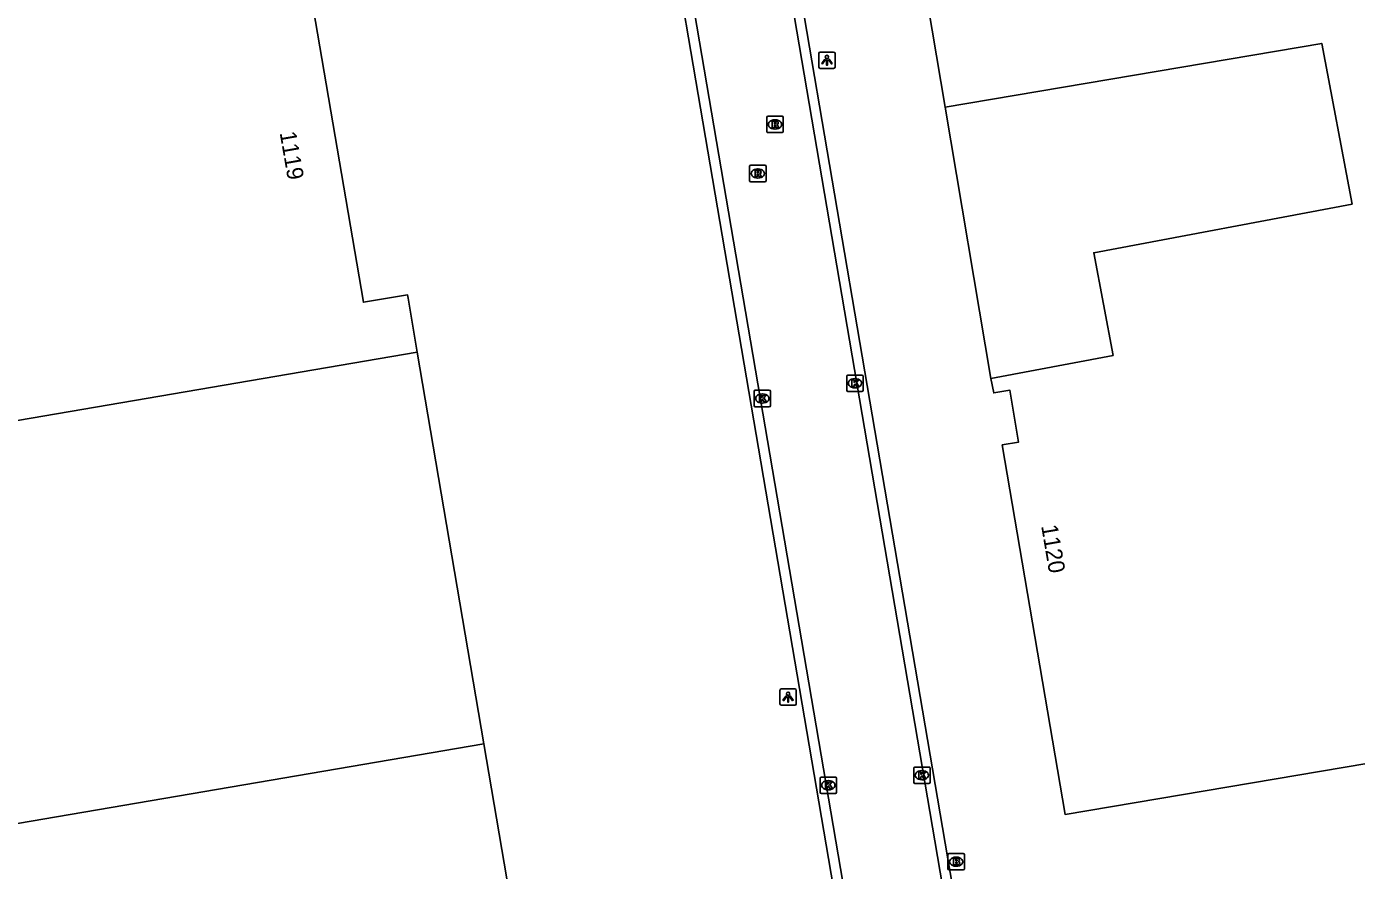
# Model space of a CAD drawing. Extents: x 154324 to 155743, y 382939 to 384183.
# Drawn here: x 154878.9 to 154959.7, y 383380.6 to 383431.9 of the extents above; entities that cross this region are included whole.
import ezdxf

# ---------------------------------------------------------------- set-up
doc = ezdxf.new("R2010")
doc.units = 0
for name, color, linetype in [('IMGEO_Brandkraan', 7, 'Continuous'), ('IMGEO_Hek', 7, 'Continuous'), ('IMGEO_Kolk', 7, 'Continuous'), ('IMGEO_Lichtpunt', 7, 'Continuous'), ('IMGEO_Pand', 7, 'Continuous'), ('IMGEO_Pand_nummerreeks', 7, 'Continuous'), ('IMGEO_Pand_overbouw', 7, 'Continuous'), ('IMGEO_Rijbaan_lokaal_gesloten', 7, 'Continuous'), ('IMGEO_Rijbaan_lokaal_open', 7, 'Continuous'), ('IMGEO_Rioolput', 7, 'Continuous')]:
    doc.layers.add(name, color=color, linetype=linetype)

msp = doc.modelspace()

# ---------------------------------------------------------------- linework, layer by layer
at = {"layer": 'IMGEO_Brandkraan'}
for p, q in [((154934.862, 383380.692), (154934.862, 383381.544)), ((154934.937, 383381.618), (154935.789, 383381.618)), ((154935.35, 383381.398), (154935.375, 383381.398)), ((154935.863, 383381.544), (154935.863, 383380.692)), ((154935.789, 383380.618), (154934.937, 383380.618)), ((154935.373, 383380.838), (154935.348, 383380.838))]:
    msp.add_line(p, q, dxfattribs=at)
for points in [[(154934.862, 383380.692), (154934.862, 383381.544)], [(154934.937, 383381.618), (154935.789, 383381.618)], [(154935.21, 383381.318), (154935.21, 383380.918), (154935.423, 383380.918)], [(154935.441, 383381.318), (154935.21, 383381.318)], [(154935.389, 383381.237), (154935.335, 383381.237), (154935.335, 383381.161)], [(154935.863, 383381.544), (154935.863, 383380.692)], [(154935.789, 383380.618), (154934.937, 383380.618)], [(154935.335, 383381.161), (154935.388, 383381.161)], [(154935.397, 383381.085), (154935.335, 383381.085), (154935.335, 383381.004)], [(154935.335, 383381.004), (154935.397, 383381.004)]]:
    msp.add_lwpolyline(points, dxfattribs=at)
for centre, radius, start, end in [((154934.939, 383381.542), 0.0765, 91.55205, 178.44795), ((154934.939, 383381.542), 0.0765, 91.55205, 178.44795), ((154935.39, 383381.199), 0.0379, 267.82845, 90.93552), ((154935.445, 383381.173), 0.145, 59.4692, 91.53667), ((154935.47, 383381.22), 0.0922, 285.51372, 58.15012), ((154935.787, 383381.542), 0.0765, 1.55205, 88.44795), ((154935.787, 383381.542), 0.0765, 1.55205, 88.44795), ((154934.939, 383380.694), 0.0765, 181.55205, 268.44795), ((154934.939, 383380.694), 0.0765, 181.55205, 268.44795), ((154935.398, 383381.044), 0.0404, 269.87594, 90.50774), ((154935.429, 383381.169), 0.251, 268.66757, 293.53466), ((154935.475, 383381.028), 0.105, 301.31148, 78.98903), ((154935.787, 383380.694), 0.0765, 271.55205, 358.44795), ((154935.787, 383380.694), 0.0765, 271.55205, 358.44795)]:
    msp.add_arc(centre, radius, start, end, dxfattribs=at)
for centre, major_axis, ratio, start_param, end_param in [((154935.349, 383381.118), (-0.387, 0.002), 0.722429, 4.712389, 7.853982), ((154935.374, 383381.118), (-0.39, 0.002), 0.717154, 1.570796, 4.712389)]:
    msp.add_ellipse(centre, major_axis=major_axis, ratio=ratio, start_param=start_param, end_param=end_param, dxfattribs=at)
at = {"layer": 'IMGEO_Hek'}
msp.add_lwpolyline([(154902.623, 383412.072), (154906.674, 383388.272)], dxfattribs=at)
at = {"layer": 'IMGEO_Kolk'}
for p, q in [((154928.715, 383409.766), (154928.715, 383410.618)), ((154928.79, 383410.692), (154929.642, 383410.692)), ((154929.203, 383410.472), (154929.228, 383410.472)), ((154929.716, 383410.618), (154929.716, 383409.766)), ((154923.088, 383408.839), (154923.088, 383409.691)), ((154923.163, 383409.765), (154924.015, 383409.765)), ((154923.576, 383409.545), (154923.601, 383409.545)), ((154924.089, 383409.691), (154924.089, 383408.839)), ((154929.642, 383409.692), (154928.79, 383409.692)), ((154929.226, 383409.912), (154929.201, 383409.912)), ((154924.015, 383408.765), (154923.163, 383408.765)), ((154923.599, 383408.985), (154923.574, 383408.985)), ((154932.859, 383386.872), (154933.711, 383386.872)), ((154927.099, 383385.338), (154927.099, 383386.19)), ((154927.174, 383386.264), (154928.026, 383386.264)), ((154928.1, 383386.19), (154928.1, 383385.338)), ((154932.784, 383385.946), (154932.784, 383386.798)), ((154933.295, 383386.092), (154933.27, 383386.092)), ((154933.272, 383386.652), (154933.297, 383386.652)), ((154933.785, 383386.798), (154933.785, 383385.946)), ((154928.026, 383385.264), (154927.174, 383385.264)), ((154927.61, 383385.484), (154927.585, 383385.484)), ((154927.587, 383386.044), (154927.612, 383386.044)), ((154933.711, 383385.872), (154932.859, 383385.872))]:
    msp.add_line(p, q, dxfattribs=at)
for points in [[(154928.715, 383409.766), (154928.715, 383410.618)], [(154928.79, 383410.692), (154929.642, 383410.692)], [(154929.036, 383410.392), (154929.159, 383410.392), (154929.159, 383410.241), (154929.289, 383410.392), (154929.453, 383410.392), (154929.307, 383410.241), (154929.46, 383409.992), (154929.308, 383409.992), (154929.223, 383410.156), (154929.159, 383410.089), (154929.159, 383409.992), (154929.036, 383409.992), (154929.036, 383410.392)], [(154929.716, 383410.618), (154929.716, 383409.766)], [(154923.088, 383408.839), (154923.088, 383409.691)], [(154923.163, 383409.765), (154924.015, 383409.765)], [(154924.089, 383409.691), (154924.089, 383408.839)], [(154929.642, 383409.692), (154928.79, 383409.692)], [(154924.015, 383408.765), (154923.163, 383408.765)], [(154923.409, 383409.465), (154923.532, 383409.465), (154923.532, 383409.314), (154923.662, 383409.465), (154923.826, 383409.465), (154923.68, 383409.314), (154923.833, 383409.065), (154923.681, 383409.065), (154923.596, 383409.229), (154923.532, 383409.162), (154923.532, 383409.065), (154923.409, 383409.065), (154923.409, 383409.465)], [(154932.859, 383386.872), (154933.711, 383386.872)], [(154927.099, 383385.338), (154927.099, 383386.19)], [(154927.174, 383386.264), (154928.026, 383386.264)], [(154928.1, 383386.19), (154928.1, 383385.338)], [(154932.784, 383385.946), (154932.784, 383386.798)], [(154933.105, 383386.572), (154933.228, 383386.572), (154933.228, 383386.421), (154933.358, 383386.572), (154933.522, 383386.572), (154933.376, 383386.421), (154933.529, 383386.172), (154933.377, 383386.172), (154933.292, 383386.336), (154933.228, 383386.269), (154933.228, 383386.172), (154933.105, 383386.172), (154933.105, 383386.572)], [(154933.785, 383386.798), (154933.785, 383385.946)], [(154928.026, 383385.264), (154927.174, 383385.264)], [(154927.42, 383385.964), (154927.543, 383385.964), (154927.543, 383385.813), (154927.673, 383385.964), (154927.837, 383385.964), (154927.691, 383385.813), (154927.844, 383385.564), (154927.692, 383385.564), (154927.607, 383385.728), (154927.543, 383385.661), (154927.543, 383385.564), (154927.42, 383385.564), (154927.42, 383385.964)], [(154933.711, 383385.872), (154932.859, 383385.872)]]:
    msp.add_lwpolyline(points, dxfattribs=at)
for centre, start, end in [((154928.792, 383410.616), 91.55205, 178.44795), ((154928.792, 383410.616), 91.55205, 178.44795), ((154929.64, 383410.616), 1.55205, 88.44795), ((154929.64, 383410.616), 1.55205, 88.44795), ((154923.165, 383409.689), 91.55205, 178.44795), ((154923.165, 383409.689), 91.55205, 178.44795), ((154924.013, 383409.689), 1.55205, 88.44795), ((154924.013, 383409.689), 1.55205, 88.44795), ((154928.792, 383409.768), 181.55205, 268.44795), ((154928.792, 383409.768), 181.55205, 268.44795), ((154929.64, 383409.768), 271.55205, 358.44795), ((154929.64, 383409.768), 271.55205, 358.44795), ((154923.165, 383408.841), 181.55205, 268.44795), ((154923.165, 383408.841), 181.55205, 268.44795), ((154924.013, 383408.841), 271.55205, 358.44795), ((154924.013, 383408.841), 271.55205, 358.44795), ((154932.861, 383386.796), 91.55205, 178.44795), ((154932.861, 383386.796), 91.55205, 178.44795), ((154933.709, 383386.796), 1.55205, 88.44795), ((154933.709, 383386.796), 1.55205, 88.44795), ((154927.176, 383386.188), 91.55205, 178.44795), ((154927.176, 383386.188), 91.55205, 178.44795), ((154928.024, 383386.188), 1.55205, 88.44795), ((154928.024, 383386.188), 1.55205, 88.44795), ((154927.176, 383385.34), 181.55205, 268.44795), ((154927.176, 383385.34), 181.55205, 268.44795), ((154928.024, 383385.34), 271.55205, 358.44795), ((154928.024, 383385.34), 271.55205, 358.44795), ((154932.861, 383385.948), 181.55205, 268.44795), ((154932.861, 383385.948), 181.55205, 268.44795), ((154933.709, 383385.948), 271.55205, 358.44795), ((154933.709, 383385.948), 271.55205, 358.44795)]:
    msp.add_arc(centre, 0.0765, start, end, dxfattribs=at)
for centre, major_axis, ratio, start_param, end_param in [((154929.202, 383410.192), (-0.387, 0.002), 0.722429, 4.712389, 7.853982), ((154929.227, 383410.192), (-0.39, 0.002), 0.717154, 1.570796, 4.712389), ((154923.575, 383409.265), (-0.387, 0.002), 0.722429, 4.712389, 7.853982), ((154923.6, 383409.265), (-0.39, 0.002), 0.717154, 1.570796, 4.712389), ((154933.271, 383386.372), (-0.387, 0.002), 0.722429, 4.712389, 7.853982), ((154933.296, 383386.372), (-0.39, 0.002), 0.717154, 1.570796, 4.712389), ((154927.586, 383385.764), (-0.387, 0.002), 0.722429, 4.712389, 7.853982), ((154927.611, 383385.764), (-0.39, 0.002), 0.717154, 1.570796, 4.712389)]:
    msp.add_ellipse(centre, major_axis=major_axis, ratio=ratio, start_param=start_param, end_param=end_param, dxfattribs=at)
at = {"layer": 'IMGEO_Lichtpunt'}
for p, q in [((154927.016, 383430.225), (154927.016, 383429.418)), ((154927.016, 383430.225), (154927.016, 383429.418)), ((154927.918, 383430.32), (154927.11, 383430.32)), ((154927.918, 383430.32), (154927.11, 383430.32)), ((154928.012, 383429.418), (154928.012, 383430.225)), ((154928.012, 383429.418), (154928.012, 383430.225)), ((154927.11, 383429.324), (154927.918, 383429.324)), ((154927.11, 383429.324), (154927.918, 383429.324)), ((154924.657, 383391.526), (154924.657, 383390.719)), ((154924.657, 383391.526), (154924.657, 383390.719)), ((154925.559, 383391.621), (154924.751, 383391.621)), ((154925.559, 383391.621), (154924.751, 383391.621)), ((154925.653, 383390.719), (154925.653, 383391.526)), ((154925.653, 383390.719), (154925.653, 383391.526)), ((154924.751, 383390.625), (154925.559, 383390.625)), ((154924.751, 383390.625), (154925.559, 383390.625))]:
    msp.add_line(p, q, dxfattribs=at)
for points in [[(154927.39, 383429.889), (154927.429, 383429.861), (154927.241, 383429.599), (154927.203, 383429.626), (154927.39, 383429.889)], [(154927.492, 383429.841), (154927.539, 383429.841), (154927.539, 383429.519), (154927.492, 383429.519), (154927.492, 383429.841)], [(154927.602, 383429.861), (154927.64, 383429.888), (154927.827, 383429.626), (154927.788, 383429.598), (154927.602, 383429.861)], [(154925.031, 383391.19), (154925.07, 383391.162), (154924.882, 383390.9), (154924.844, 383390.927), (154925.031, 383391.19)], [(154925.133, 383391.142), (154925.18, 383391.142), (154925.18, 383390.82), (154925.133, 383390.82), (154925.133, 383391.142)], [(154925.243, 383391.162), (154925.281, 383391.189), (154925.468, 383390.927), (154925.429, 383390.899), (154925.243, 383391.162)]]:
    msp.add_lwpolyline(points, dxfattribs=at)
for centre in [(154927.515, 383430.023), (154925.156, 383391.324)]:
    msp.add_circle(centre, 0.0994, dxfattribs=at)
for centre, start, end in [((154927.11, 383430.225), 90, 180), ((154927.11, 383430.225), 90, 180), ((154927.918, 383430.225), 0, 90), ((154927.918, 383430.225), 0, 90), ((154927.11, 383429.418), 180, 270), ((154927.11, 383429.418), 180, 270), ((154927.918, 383429.418), 270, 0), ((154927.918, 383429.418), 270, 360), ((154924.751, 383391.526), 90, 180), ((154924.751, 383391.526), 90, 180), ((154925.559, 383391.526), 0, 90), ((154925.559, 383391.526), 0, 90), ((154924.751, 383390.719), 180, 270), ((154924.751, 383390.719), 180, 270), ((154925.559, 383390.719), 270, 0), ((154925.559, 383390.719), 270, 360)]:
    msp.add_arc(centre, 0.0946, start, end, dxfattribs=at)
at = {"layer": 'IMGEO_Pand'}
for points in [[(154834.619, 383400.461), (154821.718, 383476.24), (154889.716, 383487.815), (154890.443, 383483.587), (154890.304, 383483.564), (154892.766, 383469.145), (154892.803, 383468.928), (154890.043, 383468.457), (154891.058, 383462.645), (154893.935, 383463.15), (154893.976, 383462.908), (154894.602, 383459.232), (154877.774, 383456.368), (154879.542, 383446.048), (154896.359, 383448.912), (154898.955, 383433.672), (154898.99, 383433.466), (154896.309, 383433.01), (154899.362, 383415.11), (154902.045, 383415.555), (154902.077, 383415.363), (154902.623, 383412.072), (154834.619, 383400.461)], [(154982.688, 383452.666), (154992.885, 383392.595), (154941.984, 383383.986), (154938.166, 383406.445), (154939.152, 383406.613), (154938.627, 383409.767), (154937.644, 383409.605), (154937.479, 383410.489), (154944.895, 383411.887), (154943.721, 383418.118), (154959.415, 383421.076), (154957.574, 383430.84), (154934.692, 383426.973), (154931.812, 383444.014), (154982.688, 383452.666)], [(154838.617, 383376.662), (154906.674, 383388.272), (154909.471, 383371.879), (154909.506, 383371.674), (154906.592, 383371.177), (154909.354, 383354.958), (154912.253, 383355.448), (154912.286, 383355.25), (154916.529, 383330.318), (154915.54, 383330.141), (154917.365, 383319.49), (154915.455, 383319.155), (154917.904, 383304.636), (154920.822, 383305.041), (154920.858, 383304.829), (154920.912, 383304.514), (154852.875, 383292.89), (154838.617, 383376.662)]]:
    msp.add_lwpolyline(points, dxfattribs=at)
at = {"layer": 'IMGEO_Pand_overbouw'}
msp.add_lwpolyline([(154957.574, 383430.84), (154934.692, 383426.973), (154937.479, 383410.489), (154944.895, 383411.887), (154943.721, 383418.118), (154959.415, 383421.076)], close=True, dxfattribs=at)
at = {"layer": 'IMGEO_Rijbaan_lokaal_gesloten'}
for points in [[(154859.21, 383821.776), (154860.592, 383813.666), (154872.994, 383740.868), (154875.261, 383727.607), (154875.734, 383724.688), (154937.891, 383359.922)], [(154854.425, 383814.31), (154854.653, 383812.991), (154854.813, 383812.024), (154858.483, 383790.497), (154869.559, 383725.258), (154869.596, 383725.133), (154932.04, 383358.964)]]:
    msp.add_lwpolyline(points, dxfattribs=at)
at = {"layer": 'IMGEO_Rijbaan_lokaal_open'}
for points in [[(154936.699, 383370.542), (154936.688, 383370.604), (154886.005, 383668.098)], [(154931.446, 383358.867), (154880.326, 383658.587), (154880.297, 383658.755)]]:
    msp.add_lwpolyline(points, dxfattribs=at)
at = {"layer": 'IMGEO_Rioolput'}
for p, q in [((154923.86, 383425.493), (154923.86, 383426.345)), ((154923.935, 383426.419), (154924.787, 383426.419)), ((154924.371, 383425.639), (154924.346, 383425.639)), ((154924.348, 383426.199), (154924.373, 383426.199)), ((154924.861, 383426.345), (154924.861, 383425.493)), ((154924.787, 383425.419), (154923.935, 383425.419)), ((154922.814, 383422.511), (154922.814, 383423.363)), ((154922.889, 383423.437), (154923.741, 383423.437)), ((154923.302, 383423.217), (154923.327, 383423.217)), ((154923.815, 383423.363), (154923.815, 383422.511)), ((154923.741, 383422.437), (154922.889, 383422.437)), ((154923.325, 383422.657), (154923.3, 383422.657))]:
    msp.add_line(p, q, dxfattribs=at)
for points in [[(154923.86, 383425.493), (154923.86, 383426.345)], [(154923.935, 383426.419), (154924.787, 383426.419)], [(154924.449, 383426.117), (154924.197, 383426.119), (154924.197, 383425.719)], [(154924.197, 383425.719), (154924.321, 383425.719), (154924.321, 383425.881), (154924.332, 383425.881)], [(154924.375, 383426.038), (154924.321, 383426.038), (154924.321, 383425.957)], [(154924.321, 383425.957), (154924.373, 383425.957)], [(154924.379, 383425.852), (154924.45, 383425.719), (154924.59, 383425.719), (154924.525, 383425.845)], [(154924.861, 383426.345), (154924.861, 383425.493)], [(154924.787, 383425.419), (154923.935, 383425.419)], [(154922.814, 383422.511), (154922.814, 383423.363)], [(154922.889, 383423.437), (154923.741, 383423.437)], [(154923.815, 383423.363), (154923.815, 383422.511)], [(154923.741, 383422.437), (154922.889, 383422.437)], [(154923.403, 383423.135), (154923.151, 383423.137), (154923.151, 383422.737)], [(154923.151, 383422.737), (154923.275, 383422.737), (154923.275, 383422.899), (154923.286, 383422.899)], [(154923.329, 383423.056), (154923.275, 383423.056), (154923.275, 383422.975)], [(154923.275, 383422.975), (154923.327, 383422.975)], [(154923.333, 383422.87), (154923.404, 383422.737), (154923.544, 383422.737), (154923.479, 383422.863)]]:
    msp.add_lwpolyline(points, dxfattribs=at)
for centre, radius, start, end in [((154923.937, 383426.343), 0.0765, 91.55205, 178.44795), ((154923.937, 383426.343), 0.0765, 91.55205, 178.44795), ((154924.331, 383425.828), 0.0533, 26.02933, 88.69889), ((154924.357, 383426.146), 0.19, 274.7715, 282.96867), ((154924.381, 383425.942), 0.0964, 77.00612, 93.18647), ((154924.395, 383425.999), 0.0378, 276.66336, 79.67722), ((154924.448, 383426.007), 0.109, 350.36119, 89.41601), ((154924.446, 383426.007), 0.112, 277.58423, 350.98172), ((154924.43, 383425.792), 0.108, 29.51342, 73.79051), ((154924.785, 383426.343), 0.0765, 1.55205, 88.44795), ((154924.785, 383426.343), 0.0765, 1.55205, 88.44795), ((154923.937, 383425.495), 0.0765, 181.55205, 268.44795), ((154923.937, 383425.495), 0.0765, 181.55205, 268.44795), ((154924.785, 383425.495), 0.0765, 271.55205, 358.44795), ((154924.785, 383425.495), 0.0765, 271.55205, 358.44795), ((154922.891, 383423.361), 0.0765, 91.55205, 178.44795), ((154922.891, 383423.361), 0.0765, 91.55205, 178.44795), ((154923.739, 383423.361), 0.0765, 1.55205, 88.44795), ((154923.739, 383423.361), 0.0765, 1.55205, 88.44795), ((154922.891, 383422.513), 0.0765, 181.55205, 268.44795), ((154922.891, 383422.513), 0.0765, 181.55205, 268.44795), ((154923.285, 383422.846), 0.0533, 26.02933, 88.69889), ((154923.311, 383423.164), 0.19, 274.7715, 282.96867), ((154923.335, 383422.96), 0.0964, 77.00612, 93.18647), ((154923.349, 383423.017), 0.0378, 276.66336, 79.67722), ((154923.402, 383423.025), 0.109, 350.36119, 89.41601), ((154923.4, 383423.025), 0.112, 277.58423, 350.98172), ((154923.384, 383422.81), 0.108, 29.51342, 73.79051), ((154923.739, 383422.513), 0.0765, 271.55205, 358.44795), ((154923.739, 383422.513), 0.0765, 271.55205, 358.44795)]:
    msp.add_arc(centre, radius, start, end, dxfattribs=at)
for centre, major_axis, ratio, start_param, end_param in [((154924.347, 383425.919), (-0.387, 0.002), 0.722429, 4.712389, 7.853982), ((154924.372, 383425.919), (-0.39, 0.002), 0.717154, 1.570796, 4.712389), ((154923.301, 383422.937), (-0.387, 0.002), 0.722429, 4.712389, 7.853982), ((154923.326, 383422.937), (-0.39, 0.002), 0.717154, 1.570796, 4.712389)]:
    msp.add_ellipse(centre, major_axis=major_axis, ratio=ratio, start_param=start_param, end_param=end_param, dxfattribs=at)

# ---------------------------------------------------------------- texts
at = {"layer": 'IMGEO_Pand_nummerreeks'}
for s, rotation, p in [('1119', 279.90878, (154894.265, 383425.417)), ('1120', 279.6484, (154940.525, 383401.521))]:
    msp.add_text(s, height=1, rotation=rotation, dxfattribs=at).set_placement(p)

doc.saveas('drawing.dxf')
